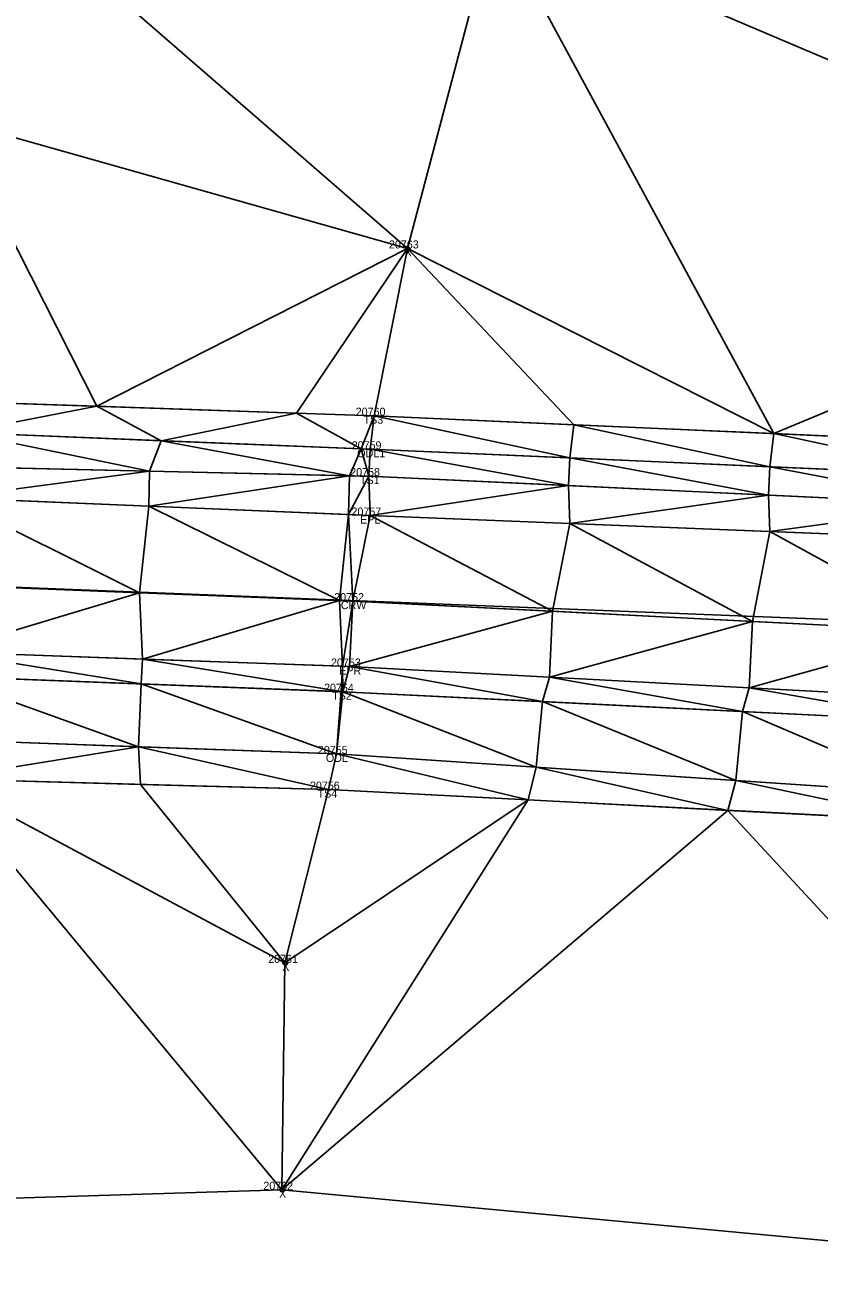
# Model space of a CAD drawing. Extents: x 1966740 to 1969291, y 1117379 to 1118460.
# Drawn here: x 1968948.1 to 1969047.3, y 1117812.7 to 1117968.4 of the extents above; entities that cross this region are included whole.
import ezdxf

# ---------------------------------------------------------------- set-up
doc = ezdxf.new("R2010")
doc.units = 0
for name, color, linetype in [('Level 1', 7, 'Continuous'), ('Level 3', 7, 'Continuous'), ('Level 30', 7, 'Continuous'), ('Level 35', 7, 'Continuous'), ('Level 50', 7, 'Continuous'), ('Level 52', 7, 'Continuous'), ('Level 53', 7, 'Continuous'), ('Level 56', 7, 'Continuous'), ('Level 6', 7, 'Continuous'), ('Level 62', 7, 'Continuous')]:
    doc.layers.add(name, color=color, linetype=linetype)

msp = doc.modelspace()

# ---------------------------------------------------------------- linework, layer by layer
at = {"layer": 'Level 1'}
msp.add_line((1968120.33, 1117930.94), (1969279.02, 1117884.95), dxfattribs=at)
at = {"layer": 'Level 3'}
for points in [[(1968531.49, 1117931.42), (1968682.06, 1117924.3), (1968783.42, 1117919.17), (1968888.7, 1117914.33), (1968991.06, 1117912.02), (1969093.07, 1117907.16), (1969191.83, 1117902.92), (1969283.72, 1117899.63)], [(1968530.54, 1117925.7), (1968681.97, 1117919.01), (1968783.23, 1117915.36), (1968888.64, 1117911.44), (1968991.22, 1117907.09), (1969091.98, 1117903.06), (1969191.09, 1117898.66), (1969283.27, 1117895.43)], [(1968882.13, 1117923.29), (1968991.72, 1117919.56), (1969094.35, 1117914.97), (1969192.08, 1117910.66), (1969282.99, 1117908.48)], [(1968529.36, 1117916.3), (1968681.48, 1117908.5), (1968781.89, 1117904.51), (1968887.49, 1117900.39), (1968989.06, 1117896.4), (1969090.87, 1117891.24), (1969190.23, 1117887.94), (1969284.4, 1117884.73)], [(1968527.82, 1117906.41), (1968680.79, 1117899.07), (1968781.71, 1117895.37), (1968887.86, 1117891.84), (1968988.65, 1117888.23), (1969090.1, 1117882.83), (1969189.3, 1117879.04), (1969282.94, 1117875.42)], [(1968528.99, 1117899.6), (1968680.45, 1117894.84), (1968781.74, 1117892.71), (1968887.7, 1117888.94), (1968987.81, 1117885.08), (1969089.75, 1117880.01), (1969189.02, 1117876.39), (1969282.76, 1117873.05)], [(1968528.68, 1117880.51), (1968680.3, 1117884.55), (1968781.05, 1117880.46), (1968887.57, 1117875.57), (1968986, 1117872.85), (1969087.95, 1117867.56), (1969189.32, 1117864.4), (1969289.73, 1117862.33)]]:
    msp.add_lwpolyline(points, dxfattribs=at)
at = {"layer": 'Level 30'}
for centre in [(1968995.87, 1117940.46), (1968980.57, 1117851.21), (1968980.18, 1117822.86)]:
    msp.add_circle(centre, 0.25, dxfattribs=at)
at = {"layer": 'Level 35'}
for points in [[(1969006.8, 1117981.76), (1969111.1, 1117985.78), (1969100.72, 1117941.88)], [(1968938.93, 1117956.53), (1968949.07, 1117981.12), (1968995.87, 1117940.46)], [(1968949.07, 1117981.12), (1969006.8, 1117981.76), (1968995.87, 1117940.46)], [(1968995.87, 1117940.46), (1969006.8, 1117981.76), (1969041.66, 1117917.33)], [(1969006.8, 1117981.76), (1969100.72, 1117941.88), (1969041.66, 1117917.33)], [(1968932.08, 1117921.59), (1968938.93, 1117956.53), (1968957.06, 1117920.74)], [(1968938.93, 1117956.53), (1968995.87, 1117940.46), (1968957.06, 1117920.74)], [(1969041.66, 1117917.33), (1969100.72, 1117941.88), (1969066.63, 1117916.21)], [(1968957.06, 1117920.74), (1968995.87, 1117940.46), (1968982.03, 1117919.89)], [(1968982.03, 1117919.89), (1968995.87, 1117940.46), (1968991.72, 1117919.56)], [(1968991.72, 1117919.56), (1968995.87, 1117940.46), (1969016.69, 1117918.44)], [(1968995.87, 1117940.46), (1969041.66, 1117917.33), (1969016.69, 1117918.44)], [(1968932.08, 1117921.59), (1968957.06, 1117920.74), (1968940.14, 1117917.45)], [(1968940.14, 1117917.45), (1968957.06, 1117920.74), (1968965.12, 1117916.43)], [(1968957.06, 1117920.74), (1968982.03, 1117919.89), (1968965.12, 1117916.43)], [(1968965.12, 1117916.43), (1968982.03, 1117919.89), (1968990.09, 1117915.41)], [(1968982.03, 1117919.89), (1968991.72, 1117919.56), (1968990.09, 1117915.41)], [(1968990.09, 1117915.41), (1968991.72, 1117919.56), (1968991.22, 1117915.37)], [(1968991.22, 1117915.37), (1968991.72, 1117919.56), (1969016.19, 1117914.28)], [(1968991.72, 1117919.56), (1969016.69, 1117918.44), (1969016.19, 1117914.28)], [(1969016.19, 1117914.28), (1969016.69, 1117918.44), (1969041.16, 1117913.19)], [(1969016.69, 1117918.44), (1969041.66, 1117917.33), (1969041.16, 1117913.19)], [(1968938.68, 1117913.2), (1968940.14, 1117917.45), (1968963.67, 1117912.63)], [(1968940.14, 1117917.45), (1968965.12, 1117916.43), (1968963.67, 1117912.63)], [(1969041.16, 1117913.19), (1969041.66, 1117917.33), (1969066.12, 1117912.1)], [(1969041.66, 1117917.33), (1969066.63, 1117916.21), (1969066.12, 1117912.1)], [(1968963.67, 1117912.63), (1968965.12, 1117916.43), (1968988.66, 1117912.07)], [(1968965.12, 1117916.43), (1968990.09, 1117915.41), (1968988.66, 1117912.07)], [(1968988.66, 1117912.07), (1968990.09, 1117915.41), (1968991.06, 1117912.02)], [(1968990.09, 1117915.41), (1968991.22, 1117915.37), (1968991.06, 1117912.02)], [(1968991.06, 1117912.02), (1968991.22, 1117915.37), (1969016.02, 1117910.83)], [(1968991.22, 1117915.37), (1969016.19, 1117914.28), (1969016.02, 1117910.83)], [(1969016.02, 1117910.83), (1969016.19, 1117914.28), (1969040.99, 1117909.64)], [(1969016.19, 1117914.28), (1969041.16, 1117913.19), (1969040.99, 1117909.64)], [(1968938.58, 1117909.32), (1968938.68, 1117913.2), (1968963.67, 1117912.63)], [(1968938.58, 1117909.32), (1968963.67, 1117912.63), (1968963.55, 1117908.26)], [(1968963.55, 1117908.26), (1968963.67, 1117912.63), (1968988.66, 1117912.07)], [(1968963.55, 1117908.26), (1968988.66, 1117912.07), (1968988.52, 1117907.2)], [(1968988.52, 1117907.2), (1968988.66, 1117912.07), (1968991.06, 1117912.02)], [(1968988.52, 1117907.2), (1968991.06, 1117912.02), (1968991.22, 1117907.09)], [(1968991.06, 1117912.02), (1969016.02, 1117910.83), (1968991.22, 1117907.09)], [(1969040.99, 1117909.64), (1969041.16, 1117913.19), (1969065.95, 1117908.45)], [(1969041.16, 1117913.19), (1969066.12, 1117912.1), (1969065.95, 1117908.45)], [(1968991.22, 1117907.09), (1969016.02, 1117910.83), (1969016.19, 1117906.09)], [(1969016.02, 1117910.83), (1969040.99, 1117909.64), (1969016.19, 1117906.09)], [(1968937.44, 1117898.43), (1968938.58, 1117909.32), (1968962.41, 1117897.45)], [(1968938.58, 1117909.32), (1968963.55, 1117908.26), (1968962.41, 1117897.45)], [(1969016.19, 1117906.09), (1969040.99, 1117909.64), (1969041.17, 1117905.09)], [(1969040.99, 1117909.64), (1969065.95, 1117908.45), (1969041.17, 1117905.09)], [(1968962.41, 1117897.45), (1968963.55, 1117908.26), (1968987.39, 1117896.47)], [(1968963.55, 1117908.26), (1968988.52, 1117907.2), (1968987.39, 1117896.47)], [(1968987.39, 1117896.47), (1968988.52, 1117907.2), (1968989.06, 1117896.4)], [(1968988.52, 1117907.2), (1968991.22, 1117907.09), (1968989.06, 1117896.4)], [(1969041.17, 1117905.09), (1969065.95, 1117908.45), (1969066.14, 1117904.1)], [(1968989.06, 1117896.4), (1968991.22, 1117907.09), (1969014.02, 1117895.14)], [(1968991.22, 1117907.09), (1969016.19, 1117906.09), (1969014.02, 1117895.14)], [(1969014.02, 1117895.14), (1969016.19, 1117906.09), (1969038.98, 1117893.87)], [(1969016.19, 1117906.09), (1969041.17, 1117905.09), (1969038.98, 1117893.87)], [(1969038.98, 1117893.87), (1969041.17, 1117905.09), (1969063.94, 1117892.61)], [(1969041.17, 1117905.09), (1969066.14, 1117904.1), (1969063.94, 1117892.61)], [(1968937.44, 1117898.43), (1968962.41, 1117897.45), (1968937.81, 1117890.05)], [(1968937.81, 1117890.05), (1968962.41, 1117897.45), (1968962.79, 1117889.16)], [(1968962.41, 1117897.45), (1968987.39, 1117896.47), (1968962.79, 1117889.16)], [(1968962.79, 1117889.16), (1968987.39, 1117896.47), (1968987.77, 1117888.26)], [(1968987.39, 1117896.47), (1968989.06, 1117896.4), (1968987.77, 1117888.26)], [(1968987.77, 1117888.26), (1968989.06, 1117896.4), (1968988.65, 1117888.23)], [(1968988.65, 1117888.23), (1968989.06, 1117896.4), (1969014.02, 1117895.14)], [(1968988.65, 1117888.23), (1969014.02, 1117895.14), (1969013.61, 1117886.9)], [(1969013.61, 1117886.9), (1969014.02, 1117895.14), (1969038.98, 1117893.87)], [(1969013.61, 1117886.9), (1969038.98, 1117893.87), (1969038.57, 1117885.57)], [(1969038.57, 1117885.57), (1969038.98, 1117893.87), (1969063.94, 1117892.61)], [(1969038.57, 1117885.57), (1969063.94, 1117892.61), (1969063.53, 1117884.25)], [(1968937.65, 1117887.01), (1968937.81, 1117890.05), (1968962.63, 1117886.05)], [(1968937.81, 1117890.05), (1968962.79, 1117889.16), (1968962.63, 1117886.05)], [(1968962.63, 1117886.05), (1968962.79, 1117889.16), (1968987.6, 1117885.09)], [(1968962.79, 1117889.16), (1968987.77, 1117888.26), (1968987.6, 1117885.09)], [(1968937.31, 1117879.1), (1968937.65, 1117887.01), (1968962.29, 1117878.2)], [(1968937.65, 1117887.01), (1968962.63, 1117886.05), (1968962.29, 1117878.2)], [(1968987.6, 1117885.09), (1968987.77, 1117888.26), (1968987.81, 1117885.08)], [(1968987.77, 1117888.26), (1968988.65, 1117888.23), (1968987.81, 1117885.08)], [(1968987.81, 1117885.08), (1968988.65, 1117888.23), (1969012.77, 1117883.84)], [(1968988.65, 1117888.23), (1969013.61, 1117886.9), (1969012.77, 1117883.84)], [(1968962.29, 1117878.2), (1968962.63, 1117886.05), (1968987.02, 1117877.31)], [(1968962.63, 1117886.05), (1968987.6, 1117885.09), (1968987.02, 1117877.31)], [(1969012.77, 1117883.84), (1969013.61, 1117886.9), (1969037.74, 1117882.6)], [(1969013.61, 1117886.9), (1969038.57, 1117885.57), (1969037.74, 1117882.6)], [(1969037.74, 1117882.6), (1969038.57, 1117885.57), (1969062.7, 1117881.36)], [(1969038.57, 1117885.57), (1969063.53, 1117884.25), (1969062.7, 1117881.36)], [(1968987.02, 1117877.31), (1968987.6, 1117885.09), (1968987.81, 1117885.08)], [(1968987.02, 1117877.31), (1968987.81, 1117885.08), (1969011.96, 1117875.64)], [(1968987.81, 1117885.08), (1969012.77, 1117883.84), (1969011.96, 1117875.64)], [(1969011.96, 1117875.64), (1969012.77, 1117883.84), (1969036.9, 1117873.98)], [(1969012.77, 1117883.84), (1969037.74, 1117882.6), (1969036.9, 1117873.98)], [(1969036.9, 1117873.98), (1969037.74, 1117882.6), (1969061.84, 1117872.31)], [(1969037.74, 1117882.6), (1969062.7, 1117881.36), (1969061.84, 1117872.31)], [(1968937.31, 1117879.1), (1968962.29, 1117878.2), (1968937.54, 1117874.19)], [(1968937.54, 1117874.19), (1968962.29, 1117878.2), (1968962.52, 1117873.5)], [(1968962.29, 1117878.2), (1968987.02, 1117877.31), (1968986, 1117872.85)], [(1968962.29, 1117878.2), (1968986, 1117872.85), (1968962.52, 1117873.5)], [(1968986, 1117872.85), (1968987.02, 1117877.31), (1969010.96, 1117871.56)], [(1968987.02, 1117877.31), (1969011.96, 1117875.64), (1969010.96, 1117871.56)], [(1969010.96, 1117871.56), (1969011.96, 1117875.64), (1969035.92, 1117870.26)], [(1969011.96, 1117875.64), (1969036.9, 1117873.98), (1969035.92, 1117870.26)], [(1968887.56, 1117819.96), (1968937.54, 1117874.19), (1968980.18, 1117822.86)], [(1968937.54, 1117874.19), (1968962.52, 1117873.5), (1968980.57, 1117851.21)], [(1968937.54, 1117874.19), (1968980.57, 1117851.21), (1968980.18, 1117822.86)], [(1968962.52, 1117873.5), (1968986, 1117872.85), (1968980.57, 1117851.21)], [(1969035.92, 1117870.26), (1969036.9, 1117873.98), (1969060.88, 1117868.97)], [(1969036.9, 1117873.98), (1969061.84, 1117872.31), (1969060.88, 1117868.97)], [(1968980.18, 1117822.86), (1968980.57, 1117851.21), (1969010.96, 1117871.56)], [(1968980.18, 1117822.86), (1969010.96, 1117871.56), (1969035.92, 1117870.26)], [(1968980.57, 1117851.21), (1968986, 1117872.85), (1969010.96, 1117871.56)], [(1968980.18, 1117822.86), (1969035.92, 1117870.26), (1969089.15, 1117812.7)], [(1969035.92, 1117870.26), (1969060.88, 1117868.97), (1969089.15, 1117812.7)]]:
    msp.add_lwpolyline(points, close=True, dxfattribs=at)
at = {"layer": 'Level 50'}
for centre in [(1968991.72, 1117919.56), (1968991.22, 1117915.37), (1968991.06, 1117912.02), (1968991.22, 1117907.09), (1968989.06, 1117896.4), (1968988.65, 1117888.23), (1968987.81, 1117885.08), (1968987.02, 1117877.31), (1968986, 1117872.85)]:
    msp.add_circle(centre, 0.001, dxfattribs=at)
at = {"layer": 'Level 6'}
for points in [[(1968531.76, 1117937.18), (1968682.22, 1117928.11), (1968784.28, 1117924.56), (1968890.2, 1117919.49), (1968991.22, 1117915.37), (1969093.76, 1117910.9), (1969192.08, 1117906.24), (1969283.24, 1117903.06)], [(1968528.55, 1117888.35), (1968679.78, 1117887.39), (1968780.67, 1117884.45), (1968887.36, 1117880.9), (1968987.02, 1117877.31), (1969088.58, 1117870.53), (1969189.53, 1117868.6), (1969284.94, 1117865.64)]]:
    msp.add_lwpolyline(points, dxfattribs=at)

# ---------------------------------------------------------------- texts
at = {"layer": 'Level 52'}
for s, p in [('20763', (1968993.57, 1117940.46)), ('20761', (1968978.48, 1117851.21)), ('20762', (1968977.88, 1117822.86))]:
    msp.add_text(s, height=1, dxfattribs=at).set_placement(p)
at = {"layer": 'Level 53'}
for s, p in [('20760', (1968989.42, 1117919.56)), ('TS3', (1968990.4, 1117918.56)), ('20759', (1968988.92, 1117915.37)), ('ODL1', (1968989.61, 1117914.37)), ('20758', (1968988.73, 1117912.02)), ('TS1', (1968989.95, 1117911.02)), ('20757', (1968988.89, 1117907.09)), ('EPL', (1968989.96, 1117906.09)), ('20752', (1968986.73, 1117896.4)), ('CRW', (1968987.56, 1117895.4)), ('20753', (1968986.33, 1117888.23)), ('EPR', (1968987.35, 1117887.23)), ('20754', (1968985.46, 1117885.08)), ('TS2', (1968986.48, 1117884.08)), ('20756', (1968983.7, 1117872.85)), ('TS4', (1968984.65, 1117871.85))]:
    msp.add_text(s, height=1, dxfattribs=at).set_placement(p)
at = {"layer": 'Level 56'}
for s, p in [('20755', (1968984.69, 1117877.31)), ('ODL', (1968985.69, 1117876.31))]:
    msp.add_text(s, height=1, dxfattribs=at).set_placement(p)
at = {"layer": 'Level 62'}
for p in [(1968995.53, 1117939.46), (1968980.23, 1117850.21), (1968979.85, 1117821.86)]:
    msp.add_text('X', height=1, dxfattribs=at).set_placement(p)

doc.saveas('drawing.dxf')
